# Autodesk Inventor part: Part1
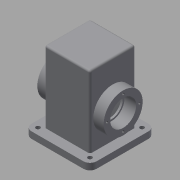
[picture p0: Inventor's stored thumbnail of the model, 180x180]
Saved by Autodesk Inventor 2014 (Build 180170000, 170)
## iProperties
Created: 2018-12
Part Number: Part1
Material: Generic
Document SubType Name: Modeling
Designer: kh
Density: 1 g/cm^3
Appearance: Default
Author: kh
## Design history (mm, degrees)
sketch "Sketch1"
  geometry: L1 (-50, -50)-(50, -50); L2 (50, -50)-(50, 50); L3 (50, 50)-(-50, 50); L4 (-50, 50)-(-50, -50); L5 (-50, -50)-(50, 50); L6 (50, -50)-(-50, 50); 1 further point
  constraints: 12 end point, 2 midpoint, 2 parallel, 1 horizontal, 1 perpendicular
  dimensions: "d0" = 100 distance of L3.end L2.end; "d1" = 100 distance of L1.end L2.end
extrude "Extrusion1" new body sketch "Sketch1" distance "d2" = 10; taper "d3" = 0 deg
sketch "Sketch2"
  geometry: L1 (-35, -35)-(35, -35); L2 (35, -35)-(35, 35); L3 (35, 35)-(-35, 35); L4 (-35, 35)-(-35, -35); L5 (-35, -35)-(35, 35); L6 (35, -35)-(-35, 35); 1 further point
  constraints: 12 end point, 2 midpoint, 2 parallel, 1 horizontal, 1 perpendicular
  dimensions: "d4" = 70 distance of L2.end L3.end; "d5" = 70 distance of L1.end L2.end
extrude "Extrusion2" join sketch "Sketch2" distance "d6" = 110; taper "d7" = 0 deg
sketch "Sketch3"
  geometry: L1 (-30, -30)-(30, -30); L2 (30, -30)-(30, 30); L3 (30, 30)-(-30, 30); L4 (-30, 30)-(-30, -30); L5 (-30, -30)-(30, 30); L6 (30, -30)-(-30, 30); 1 further point
  constraints: 12 end point, 2 midpoint, 2 parallel, 1 horizontal, 1 perpendicular
  dimensions: "d8" = 60 distance of L2.end L3.end; "d9" = 60 distance of L1.end L2.end
extrude "Extrusion3" cut sketch "Sketch3" distance "d10" = 110; taper "d11" = 0 deg
sketch "Sketch4"
  geometry: L1 (0, 70)-(110, 70) reference; L2 (0, 0)-(110, 0) reference; L3 (-10, 85)-(-10, -15) reference; L4 (-10, 35)-(45, 35); C1 r 30 at (45, 35)
  constraints: 2 end point, 1 centre point, 1 midpoint, 1 perpendicular
  dimensions: "d12" = 60 diameter of C1; "d14" = 55 distance of L4.start L4.end
extrude "Extrusion4" join sketch "Sketch4" distance "d15" = 16; taper "d16" = 0 deg
hole "Hole1" diameter "d19" = 35; stored, may be unused: countersink angle "d23" = 90 deg, drill point angle "d25" = 118 deg; dims "d17" = 10, "d18" = 10, "d20" = 6, "d21" = 40, "d22" = 18, "d24" = 26
workplane "Work Plane1"
mirror "Mirror1"
fillet "Fillet1" dims "d27" = 3
fillet "Fillet2" dims "d28" = 3
fillet "Fillet3" dims "d29" = 10
hole "Hole2" diameter "d32" = 6.5; stored, may be unused: countersink angle "d36" = 90 deg, drill point angle "d38" = 118 deg; dims "d30" = 10, "d31" = 10, "d33" = 6, "d34" = 40, "d35" = 18, "d37" = 26
hole "Hole3" diameter "d41" = 6.5; stored, may be unused: countersink angle "d45" = 90 deg, drill point angle "d47" = 118 deg; dims "d39" = 10, "d40" = 10, "d42" = 6, "d43" = 40, "d44" = 18, "d46" = 26
hole "Hole4" diameter "d50" = 6.5; stored, may be unused: countersink angle "d54" = 90 deg, drill point angle "d56" = 118 deg; dims "d48" = 10, "d49" = 10, "d51" = 6, "d52" = 40, "d53" = 18, "d55" = 26
hole "Hole5" diameter "d59" = 6.5; stored, may be unused: countersink angle "d63" = 90 deg, drill point angle "d65" = 118 deg; dims "d57" = 10, "d58" = 10, "d60" = 6, "d61" = 40, "d62" = 18, "d64" = 26
sketch "Sketch5" dims "d66" = 50
  geometry: L1 (-30, 0)-(30, 0); A1 r 30 centre (0, 0) between (-30, 0) and (30, 0) reference; 3 further points
  constraints: 2 end point, 2 point on circle, 1 coincident, 1 horizontal, 1 horizontal alignment, 1 point on line, 2 other
hole "Hole6" sketch "Sketch5" at (-25, 0) diameter "d67" = 3.242; stored, may be unused: countersink angle "d71" = 90 deg, drill point angle "d73" = 118 deg; dims "d68" = 6, "d69" = 40, "d70" = 18, "d72" = 8
pattern_circular "Circular Pattern1" dims angle "d75" = 360 deg
mirror "Mirror2"
body "Solid1"
other parameters: "d26" = 0
